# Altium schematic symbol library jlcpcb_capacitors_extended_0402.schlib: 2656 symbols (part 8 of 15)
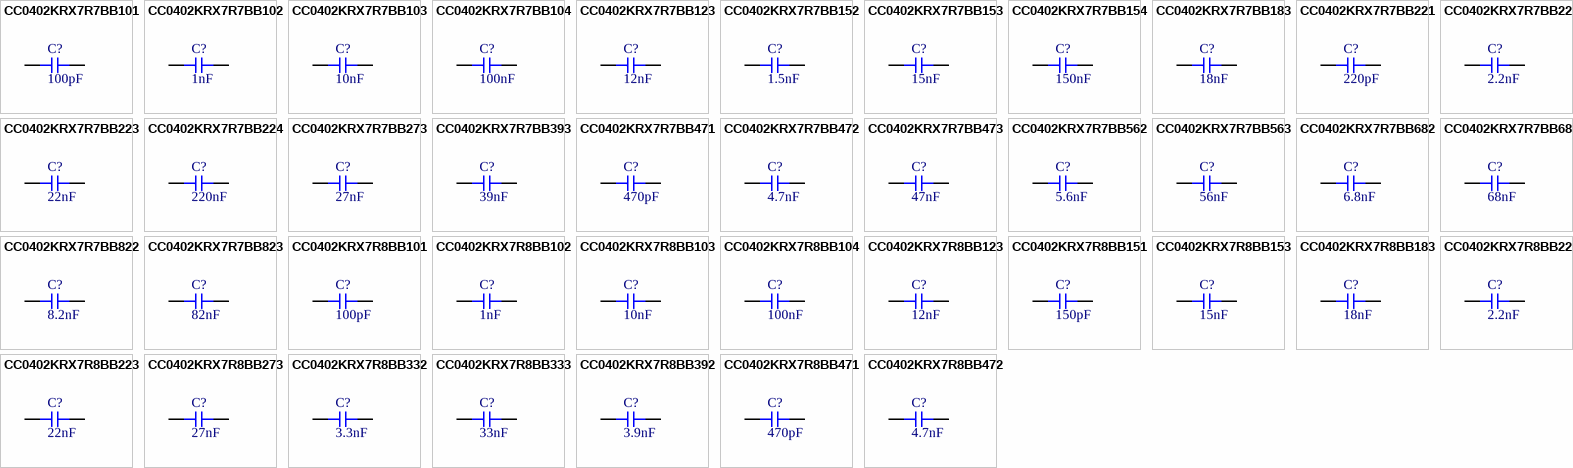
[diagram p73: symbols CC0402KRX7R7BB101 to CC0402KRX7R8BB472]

## CC0402KRX7R7BB104
designator C?  Capacitance: 100nF  (hidden comment: *)
Capacitor, Ceramic (MLCC), 100nF, ±10%, 16V, X7R, ±10%, SMD 0402; Manufacturer: YAGEO; Manufacturer Part Number: CC0402KRX7R7BB104
footprint CAP-0402 (0402 (1005M) Capacitor)
pins: 1, 2

## CC0402KRX7R7BB123
designator C?  Capacitance: 12nF  (hidden comment: *)
Capacitor, Ceramic (MLCC), 12nF, ±10%, 16V, X7R, ±10%, SMD 0402; Manufacturer: YAGEO; Manufacturer Part Number: CC0402KRX7R7BB123
footprint CAP-0402 (0402 (1005M) Capacitor)
pins: 1, 2

## CC0402KRX7R7BB152
designator C?  Capacitance: 1.5nF  (hidden comment: *)
Capacitor, Ceramic (MLCC), 1.5nF, ±10%, 16V, X7R, ±10%, SMD 0402; Manufacturer: YAGEO; Manufacturer Part Number: CC0402KRX7R7BB152
footprint CAP-0402 (0402 (1005M) Capacitor)
pins: 1, 2

## CC0402KRX7R7BB153
designator C?  Capacitance: 15nF  (hidden comment: *)
Capacitor, Ceramic (MLCC), 15nF, ±10%, 16V, X7R, ±10%, SMD 0402; Manufacturer: YAGEO; Manufacturer Part Number: CC0402KRX7R7BB153
footprint CAP-0402 (0402 (1005M) Capacitor)
pins: 1, 2

## CC0402KRX7R7BB154
designator C?  Capacitance: 150nF  (hidden comment: *)
Capacitor, Ceramic (MLCC), 150nF, ±10%, 16V, X7R, ±10%, SMD 0402; Manufacturer: YAGEO; Manufacturer Part Number: CC0402KRX7R7BB154
footprint CAP-0402 (0402 (1005M) Capacitor)
pins: 1, 2

## CC0402KRX7R7BB183
designator C?  Capacitance: 18nF  (hidden comment: *)
Capacitor, Ceramic (MLCC), 18nF, ±10%, 16V, X7R, ±10%, SMD 0402; Manufacturer: YAGEO; Manufacturer Part Number: CC0402KRX7R7BB183
footprint CAP-0402 (0402 (1005M) Capacitor)
pins: 1, 2

## CC0402KRX7R7BB221
designator C?  Capacitance: 220pF  (hidden comment: *)
Capacitor, Ceramic (MLCC), 220pF, ±10%, 16V, X7R, ±10%, SMD 0402; Manufacturer: YAGEO; Manufacturer Part Number: CC0402KRX7R7BB221
footprint CAP-0402 (0402 (1005M) Capacitor)
pins: 1, 2

## CC0402KRX7R7BB222
designator C?  Capacitance: 2.2nF  (hidden comment: *)
Capacitor, Ceramic (MLCC), 2.2nF, ±10%, 16V, X7R, ±10%, SMD 0402; Manufacturer: YAGEO; Manufacturer Part Number: CC0402KRX7R7BB222
footprint CAP-0402 (0402 (1005M) Capacitor)
pins: 1, 2

## CC0402KRX7R7BB223
designator C?  Capacitance: 22nF  (hidden comment: *)
Capacitor, Ceramic (MLCC), 22nF, ±10%, 16V, X7R, ±10%, SMD 0402; Manufacturer: YAGEO; Manufacturer Part Number: CC0402KRX7R7BB223
footprint CAP-0402 (0402 (1005M) Capacitor)
pins: 1, 2

## CC0402KRX7R7BB224
designator C?  Capacitance: 220nF  (hidden comment: *)
Capacitor, Ceramic (MLCC), 220nF, ±10%, 16V, X7R, ±10%, SMD 0402; Manufacturer: YAGEO; Manufacturer Part Number: CC0402KRX7R7BB224
footprint CAP-0402 (0402 (1005M) Capacitor)
pins: 1, 2

## CC0402KRX7R7BB273
designator C?  Capacitance: 27nF  (hidden comment: *)
Capacitor, Ceramic (MLCC), 27nF, ±10%, 16V, X7R, ±10%, SMD 0402; Manufacturer: YAGEO; Manufacturer Part Number: CC0402KRX7R7BB273
footprint CAP-0402 (0402 (1005M) Capacitor)
pins: 1, 2

## CC0402KRX7R7BB393
designator C?  Capacitance: 39nF  (hidden comment: *)
Capacitor, Ceramic (MLCC), 39nF, ±10%, 16V, X7R, ±10%, SMD 0402; Manufacturer: YAGEO; Manufacturer Part Number: CC0402KRX7R7BB393
footprint CAP-0402 (0402 (1005M) Capacitor)
pins: 1, 2

## CC0402KRX7R7BB471
designator C?  Capacitance: 470pF  (hidden comment: *)
Capacitor, Ceramic (MLCC), 470pF, ±10%, 16V, X7R, ±10%, SMD 0402; Manufacturer: YAGEO; Manufacturer Part Number: CC0402KRX7R7BB471
footprint CAP-0402 (0402 (1005M) Capacitor)
pins: 1, 2

## CC0402KRX7R7BB472
designator C?  Capacitance: 4.7nF  (hidden comment: *)
Capacitor, Ceramic (MLCC), 4.7nF, ±10%, 16V, X7R, ±10%, SMD 0402; Manufacturer: YAGEO; Manufacturer Part Number: CC0402KRX7R7BB472
footprint CAP-0402 (0402 (1005M) Capacitor)
pins: 1, 2

## CC0402KRX7R7BB473
designator C?  Capacitance: 47nF  (hidden comment: *)
Capacitor, Ceramic (MLCC), 47nF, ±10%, 16V, X7R, ±10%, SMD 0402; Manufacturer: YAGEO; Manufacturer Part Number: CC0402KRX7R7BB473
footprint CAP-0402 (0402 (1005M) Capacitor)
pins: 1, 2

## CC0402KRX7R7BB562
designator C?  Capacitance: 5.6nF  (hidden comment: *)
Capacitor, Ceramic (MLCC), 5.6nF, ±10%, 16V, X7R, ±10%, SMD 0402; Manufacturer: YAGEO; Manufacturer Part Number: CC0402KRX7R7BB562
footprint CAP-0402 (0402 (1005M) Capacitor)
pins: 1, 2

## CC0402KRX7R7BB563
designator C?  Capacitance: 56nF  (hidden comment: *)
Capacitor, Ceramic (MLCC), 56nF, ±10%, 16V, X7R, ±10%, SMD 0402; Manufacturer: YAGEO; Manufacturer Part Number: CC0402KRX7R7BB563
footprint CAP-0402 (0402 (1005M) Capacitor)
pins: 1, 2

## CC0402KRX7R7BB682
designator C?  Capacitance: 6.8nF  (hidden comment: *)
Capacitor, Ceramic (MLCC), 6.8nF, ±10%, 16V, X7R, ±10%, SMD 0402; Manufacturer: YAGEO; Manufacturer Part Number: CC0402KRX7R7BB682
footprint CAP-0402 (0402 (1005M) Capacitor)
pins: 1, 2

## CC0402KRX7R7BB683
designator C?  Capacitance: 68nF  (hidden comment: *)
Capacitor, Ceramic (MLCC), 68nF, ±10%, 16V, X7R, ±10%, SMD 0402; Manufacturer: YAGEO; Manufacturer Part Number: CC0402KRX7R7BB683
footprint CAP-0402 (0402 (1005M) Capacitor)
pins: 1, 2

## CC0402KRX7R7BB822
designator C?  Capacitance: 8.2nF  (hidden comment: *)
Capacitor, Ceramic (MLCC), 8.2nF, ±10%, 16V, X7R, ±10%, SMD 0402; Manufacturer: YAGEO; Manufacturer Part Number: CC0402KRX7R7BB822
footprint CAP-0402 (0402 (1005M) Capacitor)
pins: 1, 2

## CC0402KRX7R7BB823
designator C?  Capacitance: 82nF  (hidden comment: *)
Capacitor, Ceramic (MLCC), 82nF, ±10%, 16V, X7R, ±10%, SMD 0402; Manufacturer: YAGEO; Manufacturer Part Number: CC0402KRX7R7BB823
footprint CAP-0402 (0402 (1005M) Capacitor)
pins: 1, 2

## CC0402KRX7R8BB101
designator C?  Capacitance: 100pF  (hidden comment: *)
Capacitor, Ceramic (MLCC), 100pF, ±10%, 25V, X7R, ±10%, SMD 0402; Manufacturer: YAGEO; Manufacturer Part Number: CC0402KRX7R8BB101
footprint CAP-0402 (0402 (1005M) Capacitor)
pins: 1, 2

## CC0402KRX7R8BB102
designator C?  Capacitance: 1nF  (hidden comment: *)
Capacitor, Ceramic (MLCC), 1nF, ±10%, 25V, X7R, ±10%, SMD 0402; Manufacturer: YAGEO; Manufacturer Part Number: CC0402KRX7R8BB102
footprint CAP-0402 (0402 (1005M) Capacitor)
pins: 1, 2

## CC0402KRX7R8BB103
designator C?  Capacitance: 10nF  (hidden comment: *)
Capacitor, Ceramic (MLCC), 10nF, ±10%, 25V, X7R, ±10%, SMD 0402; Manufacturer: YAGEO; Manufacturer Part Number: CC0402KRX7R8BB103
footprint CAP-0402 (0402 (1005M) Capacitor)
pins: 1, 2

## CC0402KRX7R8BB104
designator C?  Capacitance: 100nF  (hidden comment: *)
Capacitor, Ceramic (MLCC), 100nF, ±10%, 25V, X7R, ±10%, SMD 0402; Manufacturer: YAGEO; Manufacturer Part Number: CC0402KRX7R8BB104
footprint CAP-0402 (0402 (1005M) Capacitor)
pins: 1, 2

## CC0402KRX7R8BB123
designator C?  Capacitance: 12nF  (hidden comment: *)
Capacitor, Ceramic (MLCC), 12nF, ±10%, 25V, X7R, ±10%, SMD 0402; Manufacturer: YAGEO; Manufacturer Part Number: CC0402KRX7R8BB123
footprint CAP-0402 (0402 (1005M) Capacitor)
pins: 1, 2

## CC0402KRX7R8BB151
designator C?  Capacitance: 150pF  (hidden comment: *)
Capacitor, Ceramic (MLCC), 150pF, ±10%, 25V, X7R, ±10%, SMD 0402; Manufacturer: YAGEO; Manufacturer Part Number: CC0402KRX7R8BB151
footprint CAP-0402 (0402 (1005M) Capacitor)
pins: 1, 2

## CC0402KRX7R8BB153
designator C?  Capacitance: 15nF  (hidden comment: *)
Capacitor, Ceramic (MLCC), 15nF, ±10%, 25V, X7R, ±10%, SMD 0402; Manufacturer: YAGEO; Manufacturer Part Number: CC0402KRX7R8BB153
footprint CAP-0402 (0402 (1005M) Capacitor)
pins: 1, 2

## CC0402KRX7R8BB183
designator C?  Capacitance: 18nF  (hidden comment: *)
Capacitor, Ceramic (MLCC), 18nF, ±10%, 25V, X7R, ±10%, SMD 0402; Manufacturer: YAGEO; Manufacturer Part Number: CC0402KRX7R8BB183
footprint CAP-0402 (0402 (1005M) Capacitor)
pins: 1, 2

## CC0402KRX7R8BB222
designator C?  Capacitance: 2.2nF  (hidden comment: *)
Capacitor, Ceramic (MLCC), 2.2nF, ±10%, 25V, X7R, ±10%, SMD 0402; Manufacturer: YAGEO; Manufacturer Part Number: CC0402KRX7R8BB222
footprint CAP-0402 (0402 (1005M) Capacitor)
pins: 1, 2

## CC0402KRX7R8BB223
designator C?  Capacitance: 22nF  (hidden comment: *)
Capacitor, Ceramic (MLCC), 22nF, ±10%, 25V, X7R, ±10%, SMD 0402; Manufacturer: YAGEO; Manufacturer Part Number: CC0402KRX7R8BB223
footprint CAP-0402 (0402 (1005M) Capacitor)
pins: 1, 2

## CC0402KRX7R8BB273
designator C?  Capacitance: 27nF  (hidden comment: *)
Capacitor, Ceramic (MLCC), 27nF, ±10%, 25V, X7R, ±10%, SMD 0402; Manufacturer: YAGEO; Manufacturer Part Number: CC0402KRX7R8BB273
footprint CAP-0402 (0402 (1005M) Capacitor)
pins: 1, 2

## CC0402KRX7R8BB332
designator C?  Capacitance: 3.3nF  (hidden comment: *)
Capacitor, Ceramic (MLCC), 3.3nF, ±10%, 25V, X7R, ±10%, SMD 0402; Manufacturer: YAGEO; Manufacturer Part Number: CC0402KRX7R8BB332
footprint CAP-0402 (0402 (1005M) Capacitor)
pins: 1, 2

## CC0402KRX7R8BB333
designator C?  Capacitance: 33nF  (hidden comment: *)
Capacitor, Ceramic (MLCC), 33nF, ±10%, 25V, X7R, ±10%, SMD 0402; Manufacturer: YAGEO; Manufacturer Part Number: CC0402KRX7R8BB333
footprint CAP-0402 (0402 (1005M) Capacitor)
pins: 1, 2

## CC0402KRX7R8BB392
designator C?  Capacitance: 3.9nF  (hidden comment: *)
Capacitor, Ceramic (MLCC), 3.9nF, ±10%, 25V, X7R, ±10%, SMD 0402; Manufacturer: YAGEO; Manufacturer Part Number: CC0402KRX7R8BB392
footprint CAP-0402 (0402 (1005M) Capacitor)
pins: 1, 2

## CC0402KRX7R8BB471
designator C?  Capacitance: 470pF  (hidden comment: *)
Capacitor, Ceramic (MLCC), 470pF, ±10%, 25V, X7R, ±10%, SMD 0402; Manufacturer: YAGEO; Manufacturer Part Number: CC0402KRX7R8BB471
footprint CAP-0402 (0402 (1005M) Capacitor)
pins: 1, 2

## CC0402KRX7R8BB472
designator C?  Capacitance: 4.7nF  (hidden comment: *)
Capacitor, Ceramic (MLCC), 4.7nF, ±10%, 25V, X7R, ±10%, SMD 0402; Manufacturer: YAGEO; Manufacturer Part Number: CC0402KRX7R8BB472
footprint CAP-0402 (0402 (1005M) Capacitor)
pins: 1, 2

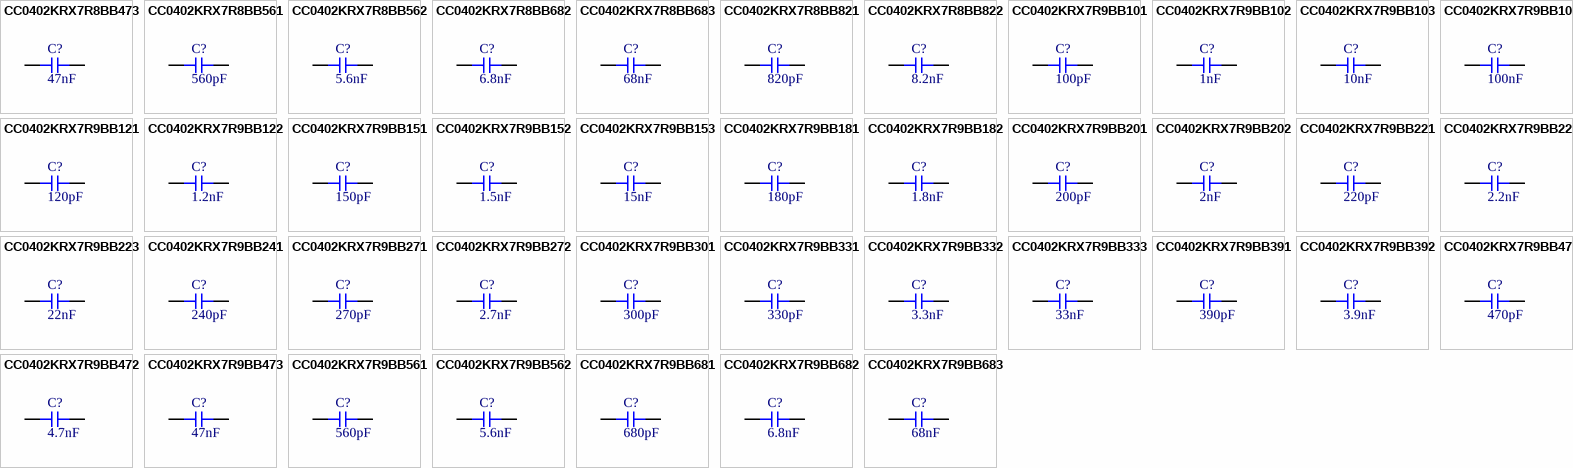
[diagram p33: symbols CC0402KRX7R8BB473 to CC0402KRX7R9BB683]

## CC0402KRX7R8BB473
designator C?  Capacitance: 47nF  (hidden comment: *)
Capacitor, Ceramic (MLCC), 47nF, ±10%, 25V, X7R, ±10%, SMD 0402; Manufacturer: YAGEO; Manufacturer Part Number: CC0402KRX7R8BB473
footprint CAP-0402 (0402 (1005M) Capacitor)
pins: 1, 2

## CC0402KRX7R8BB561
designator C?  Capacitance: 560pF  (hidden comment: *)
Capacitor, Ceramic (MLCC), 560pF, ±10%, 25V, X7R, ±10%, SMD 0402; Manufacturer: YAGEO; Manufacturer Part Number: CC0402KRX7R8BB561
footprint CAP-0402 (0402 (1005M) Capacitor)
pins: 1, 2

## CC0402KRX7R8BB562
designator C?  Capacitance: 5.6nF  (hidden comment: *)
Capacitor, Ceramic (MLCC), 5.6nF, ±10%, 25V, X7R, ±10%, SMD 0402; Manufacturer: YAGEO; Manufacturer Part Number: CC0402KRX7R8BB562
footprint CAP-0402 (0402 (1005M) Capacitor)
pins: 1, 2

## CC0402KRX7R8BB682
designator C?  Capacitance: 6.8nF  (hidden comment: *)
Capacitor, Ceramic (MLCC), 6.8nF, ±10%, 25V, X7R, ±10%, SMD 0402; Manufacturer: YAGEO; Manufacturer Part Number: CC0402KRX7R8BB682
footprint CAP-0402 (0402 (1005M) Capacitor)
pins: 1, 2

## CC0402KRX7R8BB683
designator C?  Capacitance: 68nF  (hidden comment: *)
Capacitor, Ceramic (MLCC), 68nF, ±10%, 25V, X7R, ±10%, SMD 0402; Manufacturer: YAGEO; Manufacturer Part Number: CC0402KRX7R8BB683
footprint CAP-0402 (0402 (1005M) Capacitor)
pins: 1, 2

## CC0402KRX7R8BB821
designator C?  Capacitance: 820pF  (hidden comment: *)
Capacitor, Ceramic (MLCC), 820pF, ±10%, 25V, X7R, ±10%, SMD 0402; Manufacturer: YAGEO; Manufacturer Part Number: CC0402KRX7R8BB821
footprint CAP-0402 (0402 (1005M) Capacitor)
pins: 1, 2

## CC0402KRX7R8BB822
designator C?  Capacitance: 8.2nF  (hidden comment: *)
Capacitor, Ceramic (MLCC), 8.2nF, ±10%, 25V, X7R, ±10%, SMD 0402; Manufacturer: YAGEO; Manufacturer Part Number: CC0402KRX7R8BB822
footprint CAP-0402 (0402 (1005M) Capacitor)
pins: 1, 2

## CC0402KRX7R9BB101
designator C?  Capacitance: 100pF  (hidden comment: *)
Capacitor, Ceramic (MLCC), 100pF, ±10%, 50V, X7R, ±10%, SMD 0402; Manufacturer: YAGEO; Manufacturer Part Number: CC0402KRX7R9BB101
footprint CAP-0402 (0402 (1005M) Capacitor)
pins: 1, 2

## CC0402KRX7R9BB102
designator C?  Capacitance: 1nF  (hidden comment: *)
Capacitor, Ceramic (MLCC), 1nF, ±10%, 50V, X7R, ±10%, SMD 0402; Manufacturer: YAGEO; Manufacturer Part Number: CC0402KRX7R9BB102
footprint CAP-0402 (0402 (1005M) Capacitor)
pins: 1, 2

## CC0402KRX7R9BB103
designator C?  Capacitance: 10nF  (hidden comment: *)
Capacitor, Ceramic (MLCC), 10nF, ±10%, 50V, X7R, ±10%, SMD 0402; Manufacturer: YAGEO; Manufacturer Part Number: CC0402KRX7R9BB103
footprint CAP-0402 (0402 (1005M) Capacitor)
pins: 1, 2

## CC0402KRX7R9BB104
designator C?  Capacitance: 100nF  (hidden comment: *)
Capacitor, Ceramic (MLCC), 100nF, ±10%, 50V, X7R, ±10%, SMD 0402; Manufacturer: YAGEO; Manufacturer Part Number: CC0402KRX7R9BB104
footprint CAP-0402 (0402 (1005M) Capacitor)
pins: 1, 2

## CC0402KRX7R9BB121
designator C?  Capacitance: 120pF  (hidden comment: *)
Capacitor, Ceramic (MLCC), 120pF, ±10%, 50V, X7R, ±10%, SMD 0402; Manufacturer: YAGEO; Manufacturer Part Number: CC0402KRX7R9BB121
footprint CAP-0402 (0402 (1005M) Capacitor)
pins: 1, 2

## CC0402KRX7R9BB122
designator C?  Capacitance: 1.2nF  (hidden comment: *)
Capacitor, Ceramic (MLCC), 1.2nF, ±10%, 50V, X7R, ±10%, SMD 0402; Manufacturer: YAGEO; Manufacturer Part Number: CC0402KRX7R9BB122
footprint CAP-0402 (0402 (1005M) Capacitor)
pins: 1, 2

## CC0402KRX7R9BB151
designator C?  Capacitance: 150pF  (hidden comment: *)
Capacitor, Ceramic (MLCC), 150pF, ±10%, 50V, X7R, ±10%, SMD 0402; Manufacturer: YAGEO; Manufacturer Part Number: CC0402KRX7R9BB151
footprint CAP-0402 (0402 (1005M) Capacitor)
pins: 1, 2

## CC0402KRX7R9BB152
designator C?  Capacitance: 1.5nF  (hidden comment: *)
Capacitor, Ceramic (MLCC), 1.5nF, ±10%, 50V, X7R, ±10%, SMD 0402; Manufacturer: YAGEO; Manufacturer Part Number: CC0402KRX7R9BB152
footprint CAP-0402 (0402 (1005M) Capacitor)
pins: 1, 2

## CC0402KRX7R9BB153
designator C?  Capacitance: 15nF  (hidden comment: *)
Capacitor, Ceramic (MLCC), 15nF, ±10%, 50V, X7R, ±10%, SMD 0402; Manufacturer: YAGEO; Manufacturer Part Number: CC0402KRX7R9BB153
footprint CAP-0402 (0402 (1005M) Capacitor)
pins: 1, 2

## CC0402KRX7R9BB181
designator C?  Capacitance: 180pF  (hidden comment: *)
Capacitor, Ceramic (MLCC), 180pF, ±10%, 50V, X7R, ±10%, SMD 0402; Manufacturer: YAGEO; Manufacturer Part Number: CC0402KRX7R9BB181
footprint CAP-0402 (0402 (1005M) Capacitor)
pins: 1, 2

## CC0402KRX7R9BB182
designator C?  Capacitance: 1.8nF  (hidden comment: *)
Capacitor, Ceramic (MLCC), 1.8nF, ±10%, 50V, X7R, ±10%, SMD 0402; Manufacturer: YAGEO; Manufacturer Part Number: CC0402KRX7R9BB182
footprint CAP-0402 (0402 (1005M) Capacitor)
pins: 1, 2

## CC0402KRX7R9BB201
designator C?  Capacitance: 200pF  (hidden comment: *)
Capacitor, Ceramic (MLCC), 200pF, ±10%, 50V, X7R, ±10%, SMD 0402; Manufacturer: YAGEO; Manufacturer Part Number: CC0402KRX7R9BB201
footprint CAP-0402 (0402 (1005M) Capacitor)
pins: 1, 2

## CC0402KRX7R9BB202
designator C?  Capacitance: 2nF  (hidden comment: *)
Capacitor, Ceramic (MLCC), 2nF, ±10%, 50V, X7R, ±10%, SMD 0402; Manufacturer: YAGEO; Manufacturer Part Number: CC0402KRX7R9BB202
footprint CAP-0402 (0402 (1005M) Capacitor)
pins: 1, 2

## CC0402KRX7R9BB221
designator C?  Capacitance: 220pF  (hidden comment: *)
Capacitor, Ceramic (MLCC), 220pF, ±10%, 50V, X7R, ±10%, SMD 0402; Manufacturer: YAGEO; Manufacturer Part Number: CC0402KRX7R9BB221
footprint CAP-0402 (0402 (1005M) Capacitor)
pins: 1, 2

## CC0402KRX7R9BB222
designator C?  Capacitance: 2.2nF  (hidden comment: *)
Capacitor, Ceramic (MLCC), 2.2nF, ±10%, 50V, X7R, ±10%, SMD 0402; Manufacturer: YAGEO; Manufacturer Part Number: CC0402KRX7R9BB222
footprint CAP-0402 (0402 (1005M) Capacitor)
pins: 1, 2

## CC0402KRX7R9BB223
designator C?  Capacitance: 22nF  (hidden comment: *)
Capacitor, Ceramic (MLCC), 22nF, ±10%, 50V, X7R, ±10%, SMD 0402; Manufacturer: YAGEO; Manufacturer Part Number: CC0402KRX7R9BB223
footprint CAP-0402 (0402 (1005M) Capacitor)
pins: 1, 2

## CC0402KRX7R9BB241
designator C?  Capacitance: 240pF  (hidden comment: *)
Capacitor, Ceramic (MLCC), 240pF, ±10%, 50V, X7R, ±10%, SMD 0402; Manufacturer: YAGEO; Manufacturer Part Number: CC0402KRX7R9BB241
footprint CAP-0402 (0402 (1005M) Capacitor)
pins: 1, 2

## CC0402KRX7R9BB271
designator C?  Capacitance: 270pF  (hidden comment: *)
Capacitor, Ceramic (MLCC), 270pF, ±10%, 50V, X7R, ±10%, SMD 0402; Manufacturer: YAGEO; Manufacturer Part Number: CC0402KRX7R9BB271
footprint CAP-0402 (0402 (1005M) Capacitor)
pins: 1, 2

## CC0402KRX7R9BB272
designator C?  Capacitance: 2.7nF  (hidden comment: *)
Capacitor, Ceramic (MLCC), 2.7nF, ±10%, 50V, X7R, ±10%, SMD 0402; Manufacturer: YAGEO; Manufacturer Part Number: CC0402KRX7R9BB272
footprint CAP-0402 (0402 (1005M) Capacitor)
pins: 1, 2

## CC0402KRX7R9BB301
designator C?  Capacitance: 300pF  (hidden comment: *)
Capacitor, Ceramic (MLCC), 300pF, ±10%, 50V, X7R, ±10%, SMD 0402; Manufacturer: YAGEO; Manufacturer Part Number: CC0402KRX7R9BB301
footprint CAP-0402 (0402 (1005M) Capacitor)
pins: 1, 2

## CC0402KRX7R9BB331
designator C?  Capacitance: 330pF  (hidden comment: *)
Capacitor, Ceramic (MLCC), 330pF, ±10%, 50V, X7R, ±10%, SMD 0402; Manufacturer: YAGEO; Manufacturer Part Number: CC0402KRX7R9BB331
footprint CAP-0402 (0402 (1005M) Capacitor)
pins: 1, 2

## CC0402KRX7R9BB332
designator C?  Capacitance: 3.3nF  (hidden comment: *)
Capacitor, Ceramic (MLCC), 3.3nF, ±10%, 50V, X7R, ±10%, SMD 0402; Manufacturer: YAGEO; Manufacturer Part Number: CC0402KRX7R9BB332
footprint CAP-0402 (0402 (1005M) Capacitor)
pins: 1, 2

## CC0402KRX7R9BB333
designator C?  Capacitance: 33nF  (hidden comment: *)
Capacitor, Ceramic (MLCC), 33nF, ±10%, 50V, X7R, ±10%, SMD 0402; Manufacturer: YAGEO; Manufacturer Part Number: CC0402KRX7R9BB333
footprint CAP-0402 (0402 (1005M) Capacitor)
pins: 1, 2

## CC0402KRX7R9BB391
designator C?  Capacitance: 390pF  (hidden comment: *)
Capacitor, Ceramic (MLCC), 390pF, ±10%, 50V, X7R, ±10%, SMD 0402; Manufacturer: YAGEO; Manufacturer Part Number: CC0402KRX7R9BB391
footprint CAP-0402 (0402 (1005M) Capacitor)
pins: 1, 2

## CC0402KRX7R9BB392
designator C?  Capacitance: 3.9nF  (hidden comment: *)
Capacitor, Ceramic (MLCC), 3.9nF, ±10%, 50V, X7R, ±10%, SMD 0402; Manufacturer: YAGEO; Manufacturer Part Number: CC0402KRX7R9BB392
footprint CAP-0402 (0402 (1005M) Capacitor)
pins: 1, 2

## CC0402KRX7R9BB471
designator C?  Capacitance: 470pF  (hidden comment: *)
Capacitor, Ceramic (MLCC), 470pF, ±10%, 50V, X7R, ±10%, SMD 0402; Manufacturer: YAGEO; Manufacturer Part Number: CC0402KRX7R9BB471
footprint CAP-0402 (0402 (1005M) Capacitor)
pins: 1, 2

## CC0402KRX7R9BB472
designator C?  Capacitance: 4.7nF  (hidden comment: *)
Capacitor, Ceramic (MLCC), 4.7nF, ±10%, 50V, X7R, ±10%, SMD 0402; Manufacturer: YAGEO; Manufacturer Part Number: CC0402KRX7R9BB472
footprint CAP-0402 (0402 (1005M) Capacitor)
pins: 1, 2

## CC0402KRX7R9BB473
designator C?  Capacitance: 47nF  (hidden comment: *)
Capacitor, Ceramic (MLCC), 47nF, ±10%, 50V, X7R, ±10%, SMD 0402; Manufacturer: YAGEO; Manufacturer Part Number: CC0402KRX7R9BB473
footprint CAP-0402 (0402 (1005M) Capacitor)
pins: 1, 2

## CC0402KRX7R9BB561
designator C?  Capacitance: 560pF  (hidden comment: *)
Capacitor, Ceramic (MLCC), 560pF, ±10%, 50V, X7R, ±10%, SMD 0402; Manufacturer: YAGEO; Manufacturer Part Number: CC0402KRX7R9BB561
footprint CAP-0402 (0402 (1005M) Capacitor)
pins: 1, 2

## CC0402KRX7R9BB562
designator C?  Capacitance: 5.6nF  (hidden comment: *)
Capacitor, Ceramic (MLCC), 5.6nF, ±10%, 50V, X7R, ±10%, SMD 0402; Manufacturer: YAGEO; Manufacturer Part Number: CC0402KRX7R9BB562
footprint CAP-0402 (0402 (1005M) Capacitor)
pins: 1, 2

## CC0402KRX7R9BB681
designator C?  Capacitance: 680pF  (hidden comment: *)
Capacitor, Ceramic (MLCC), 680pF, ±10%, 50V, X7R, ±10%, SMD 0402; Manufacturer: YAGEO; Manufacturer Part Number: CC0402KRX7R9BB681
footprint CAP-0402 (0402 (1005M) Capacitor)
pins: 1, 2

## CC0402KRX7R9BB682
designator C?  Capacitance: 6.8nF  (hidden comment: *)
Capacitor, Ceramic (MLCC), 6.8nF, ±10%, 50V, X7R, ±10%, SMD 0402; Manufacturer: YAGEO; Manufacturer Part Number: CC0402KRX7R9BB682
footprint CAP-0402 (0402 (1005M) Capacitor)
pins: 1, 2

## CC0402KRX7R9BB683
designator C?  Capacitance: 68nF  (hidden comment: *)
Capacitor, Ceramic (MLCC), 68nF, ±10%, 50V, X7R, ±10%, SMD 0402; Manufacturer: YAGEO; Manufacturer Part Number: CC0402KRX7R9BB683
footprint CAP-0402 (0402 (1005M) Capacitor)
pins: 1, 2

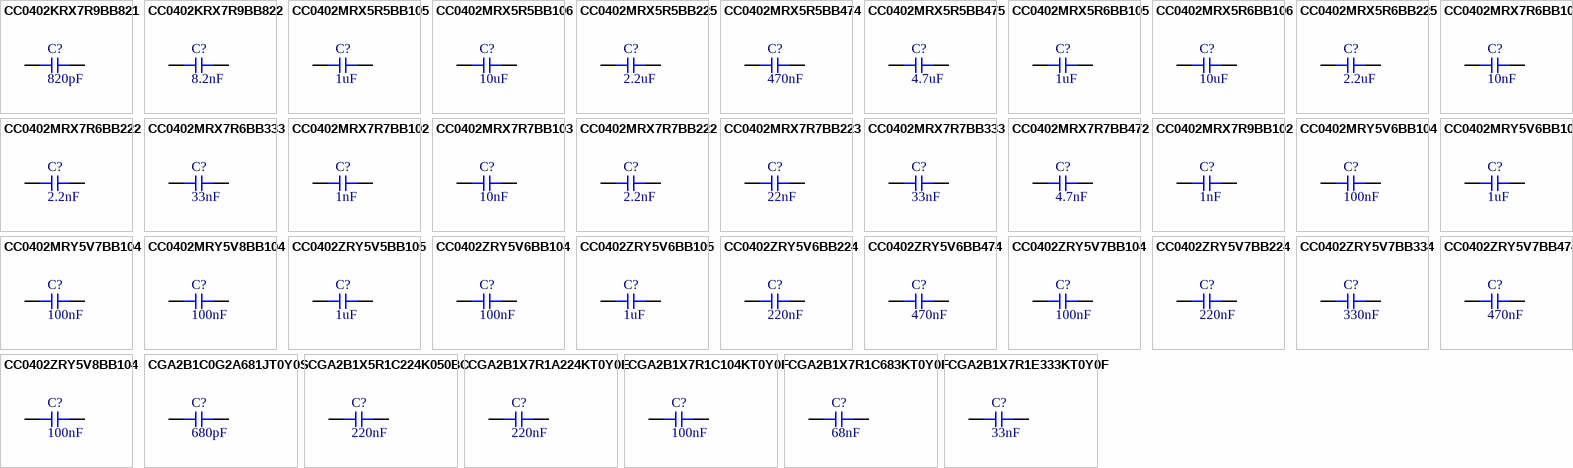
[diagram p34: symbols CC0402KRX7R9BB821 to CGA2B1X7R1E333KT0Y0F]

## CC0402KRX7R9BB821
designator C?  Capacitance: 820pF  (hidden comment: *)
Capacitor, Ceramic (MLCC), 820pF, ±10%, 50V, X7R, ±10%, SMD 0402; Manufacturer: YAGEO; Manufacturer Part Number: CC0402KRX7R9BB821
footprint CAP-0402 (0402 (1005M) Capacitor)
pins: 1, 2

## CC0402KRX7R9BB822
designator C?  Capacitance: 8.2nF  (hidden comment: *)
Capacitor, Ceramic (MLCC), 8.2nF, ±10%, 50V, X7R, ±10%, SMD 0402; Manufacturer: YAGEO; Manufacturer Part Number: CC0402KRX7R9BB822
footprint CAP-0402 (0402 (1005M) Capacitor)
pins: 1, 2

## CC0402MRX5R5BB105
designator C?  Capacitance: 1uF  (hidden comment: *)
Capacitor, Ceramic (MLCC), 1uF, ±20%, 6.3V, X5R, ±20%, SMD 0402; Manufacturer: YAGEO; Manufacturer Part Number: CC0402MRX5R5BB105
footprint CAP-0402 (0402 (1005M) Capacitor)
pins: 1, 2

## CC0402MRX5R5BB106
designator C?  Capacitance: 10uF  (hidden comment: *)
Capacitor, Ceramic (MLCC), 10uF, ±20%, 6.3V, X5R, ±20%, SMD 0402; Manufacturer: YAGEO; Manufacturer Part Number: CC0402MRX5R5BB106
footprint CAP-0402 (0402 (1005M) Capacitor)
pins: 1, 2

## CC0402MRX5R5BB225
designator C?  Capacitance: 2.2uF  (hidden comment: *)
Capacitor, Ceramic (MLCC), 2.2uF, ±20%, 6.3V, X5R, ±20%, SMD 0402; Manufacturer: YAGEO; Manufacturer Part Number: CC0402MRX5R5BB225
footprint CAP-0402 (0402 (1005M) Capacitor)
pins: 1, 2

## CC0402MRX5R5BB474
designator C?  Capacitance: 470nF  (hidden comment: *)
Capacitor, Ceramic (MLCC), 470nF, ±20%, 6.3V, X5R, ±20%, SMD 0402; Manufacturer: YAGEO; Manufacturer Part Number: CC0402MRX5R5BB474
footprint CAP-0402 (0402 (1005M) Capacitor)
pins: 1, 2

## CC0402MRX5R5BB475
designator C?  Capacitance: 4.7uF  (hidden comment: *)
Capacitor, Ceramic (MLCC), 4.7uF, ±20%, 6.3V, X5R, ±20%, SMD 0402; Manufacturer: YAGEO; Manufacturer Part Number: CC0402MRX5R5BB475
footprint CAP-0402 (0402 (1005M) Capacitor)
pins: 1, 2

## CC0402MRX5R6BB105
designator C?  Capacitance: 1uF  (hidden comment: *)
Capacitor, Ceramic (MLCC), 1uF, ±20%, 10V, X5R, ±20%, SMD 0402; Manufacturer: YAGEO; Manufacturer Part Number: CC0402MRX5R6BB105
footprint CAP-0402 (0402 (1005M) Capacitor)
pins: 1, 2

## CC0402MRX5R6BB106
designator C?  Capacitance: 10uF  (hidden comment: *)
Capacitor, Ceramic (MLCC), 10uF, ±20%, 10V, X5R, ±20%, SMD 0402; Manufacturer: YAGEO; Manufacturer Part Number: CC0402MRX5R6BB106
footprint CAP-0402 (0402 (1005M) Capacitor)
pins: 1, 2

## CC0402MRX5R6BB225
designator C?  Capacitance: 2.2uF  (hidden comment: *)
Capacitor, Ceramic (MLCC), 2.2uF, ±20%, 10V, X5R, ±20%, SMD 0402; Manufacturer: YAGEO; Manufacturer Part Number: CC0402MRX5R6BB225
footprint CAP-0402 (0402 (1005M) Capacitor)
pins: 1, 2

## CC0402MRX7R6BB103
designator C?  Capacitance: 10nF  (hidden comment: *)
Capacitor, Ceramic (MLCC), 10nF, ±20%, 10V, X7R, ±20%, SMD 0402; Manufacturer: YAGEO; Manufacturer Part Number: CC0402MRX7R6BB103
footprint CAP-0402 (0402 (1005M) Capacitor)
pins: 1, 2

## CC0402MRX7R6BB222
designator C?  Capacitance: 2.2nF  (hidden comment: *)
Capacitor, Ceramic (MLCC), 2.2nF, ±20%, 10V, X7R, ±20%, SMD 0402; Manufacturer: YAGEO; Manufacturer Part Number: CC0402MRX7R6BB222
footprint CAP-0402 (0402 (1005M) Capacitor)
pins: 1, 2

## CC0402MRX7R6BB333
designator C?  Capacitance: 33nF  (hidden comment: *)
Capacitor, Ceramic (MLCC), 33nF, ±20%, 10V, X7R, ±20%, SMD 0402; Manufacturer: YAGEO; Manufacturer Part Number: CC0402MRX7R6BB333
footprint CAP-0402 (0402 (1005M) Capacitor)
pins: 1, 2

## CC0402MRX7R7BB102
designator C?  Capacitance: 1nF  (hidden comment: *)
Capacitor, Ceramic (MLCC), 1nF, ±20%, 16V, X7R, ±20%, SMD 0402; Manufacturer: YAGEO; Manufacturer Part Number: CC0402MRX7R7BB102
footprint CAP-0402 (0402 (1005M) Capacitor)
pins: 1, 2

## CC0402MRX7R7BB103
designator C?  Capacitance: 10nF  (hidden comment: *)
Capacitor, Ceramic (MLCC), 10nF, ±20%, 16V, X7R, ±20%, SMD 0402; Manufacturer: YAGEO; Manufacturer Part Number: CC0402MRX7R7BB103
footprint CAP-0402 (0402 (1005M) Capacitor)
pins: 1, 2

## CC0402MRX7R7BB222
designator C?  Capacitance: 2.2nF  (hidden comment: *)
Capacitor, Ceramic (MLCC), 2.2nF, ±20%, 16V, X7R, ±20%, SMD 0402; Manufacturer: YAGEO; Manufacturer Part Number: CC0402MRX7R7BB222
footprint CAP-0402 (0402 (1005M) Capacitor)
pins: 1, 2

## CC0402MRX7R7BB223
designator C?  Capacitance: 22nF  (hidden comment: *)
Capacitor, Ceramic (MLCC), 22nF, ±20%, 16V, X7R, ±20%, SMD 0402; Manufacturer: YAGEO; Manufacturer Part Number: CC0402MRX7R7BB223
footprint CAP-0402 (0402 (1005M) Capacitor)
pins: 1, 2

## CC0402MRX7R7BB333
designator C?  Capacitance: 33nF  (hidden comment: *)
Capacitor, Ceramic (MLCC), 33nF, ±20%, 16V, X7R, ±20%, SMD 0402; Manufacturer: YAGEO; Manufacturer Part Number: CC0402MRX7R7BB333
footprint CAP-0402 (0402 (1005M) Capacitor)
pins: 1, 2

## CC0402MRX7R7BB472
designator C?  Capacitance: 4.7nF  (hidden comment: *)
Capacitor, Ceramic (MLCC), 4.7nF, ±20%, 16V, X7R, ±20%, SMD 0402; Manufacturer: YAGEO; Manufacturer Part Number: CC0402MRX7R7BB472
footprint CAP-0402 (0402 (1005M) Capacitor)
pins: 1, 2

## CC0402MRX7R9BB102
designator C?  Capacitance: 1nF  (hidden comment: *)
Capacitor, Ceramic (MLCC), 1nF, ±20%, 50V, X7R, ±20%, SMD 0402; Manufacturer: YAGEO; Manufacturer Part Number: CC0402MRX7R9BB102
footprint CAP-0402 (0402 (1005M) Capacitor)
pins: 1, 2

## CC0402MRY5V6BB104
designator C?  Capacitance: 100nF  (hidden comment: *)
Capacitor, Ceramic (MLCC), 100nF, ±20%, 10V, Y5V, ±20%, SMD 0402; Manufacturer: YAGEO; Manufacturer Part Number: CC0402MRY5V6BB104
footprint CAP-0402 (0402 (1005M) Capacitor)
pins: 1, 2

## CC0402MRY5V6BB105
designator C?  Capacitance: 1uF  (hidden comment: *)
Capacitor, Ceramic (MLCC), 1uF, ±20%, 10V, Y5V, ±20%, SMD 0402; Manufacturer: YAGEO; Manufacturer Part Number: CC0402MRY5V6BB105
footprint CAP-0402 (0402 (1005M) Capacitor)
pins: 1, 2

## CC0402MRY5V7BB104
designator C?  Capacitance: 100nF  (hidden comment: *)
Capacitor, Ceramic (MLCC), 100nF, ±20%, 16V, Y5V, ±20%, SMD 0402; Manufacturer: YAGEO; Manufacturer Part Number: CC0402MRY5V7BB104
footprint CAP-0402 (0402 (1005M) Capacitor)
pins: 1, 2

## CC0402MRY5V8BB104
designator C?  Capacitance: 100nF  (hidden comment: *)
Capacitor, Ceramic (MLCC), 100nF, ±20%, 25V, Y5V, ±20%, SMD 0402; Manufacturer: YAGEO; Manufacturer Part Number: CC0402MRY5V8BB104
footprint CAP-0402 (0402 (1005M) Capacitor)
pins: 1, 2

## CC0402ZRY5V5BB105
designator C?  Capacitance: 1uF  (hidden comment: *)
Capacitor, Ceramic (MLCC), 1uF, 6.3V, Y5V, SMD 0402; Manufacturer: YAGEO; Manufacturer Part Number: CC0402ZRY5V5BB105; Temperature Rating: -20%~+80%
footprint CAP-0402 (0402 (1005M) Capacitor)
pins: 1, 2

## CC0402ZRY5V6BB104
designator C?  Capacitance: 100nF  (hidden comment: *)
Capacitor, Ceramic (MLCC), 100nF, 10V, Y5V, SMD 0402; Manufacturer: YAGEO; Manufacturer Part Number: CC0402ZRY5V6BB104; Temperature Rating: -20%~+80%
footprint CAP-0402 (0402 (1005M) Capacitor)
pins: 1, 2

## CC0402ZRY5V6BB105
designator C?  Capacitance: 1uF  (hidden comment: *)
Capacitor, Ceramic (MLCC), 1uF, 10V, Y5V, SMD 0402; Manufacturer: YAGEO; Manufacturer Part Number: CC0402ZRY5V6BB105; Temperature Rating: -20%~+80%
footprint CAP-0402 (0402 (1005M) Capacitor)
pins: 1, 2

## CC0402ZRY5V6BB224
designator C?  Capacitance: 220nF  (hidden comment: *)
Capacitor, Ceramic (MLCC), 220nF, 10V, Y5V, SMD 0402; Manufacturer: YAGEO; Manufacturer Part Number: CC0402ZRY5V6BB224; Temperature Rating: -20%~+80%
footprint CAP-0402 (0402 (1005M) Capacitor)
pins: 1, 2

## CC0402ZRY5V6BB474
designator C?  Capacitance: 470nF  (hidden comment: *)
Capacitor, Ceramic (MLCC), 470nF, 10V, Y5V, SMD 0402; Manufacturer: YAGEO; Manufacturer Part Number: CC0402ZRY5V6BB474; Temperature Rating: -20%~+80%
footprint CAP-0402 (0402 (1005M) Capacitor)
pins: 1, 2

## CC0402ZRY5V7BB104
designator C?  Capacitance: 100nF  (hidden comment: *)
Capacitor, Ceramic (MLCC), 100nF, 16V, Y5V, SMD 0402; Manufacturer: YAGEO; Manufacturer Part Number: CC0402ZRY5V7BB104; Temperature Rating: -20%~+80%
footprint CAP-0402 (0402 (1005M) Capacitor)
pins: 1, 2

## CC0402ZRY5V7BB224
designator C?  Capacitance: 220nF  (hidden comment: *)
Capacitor, Ceramic (MLCC), 220nF, 16V, Y5V, SMD 0402; Manufacturer: YAGEO; Manufacturer Part Number: CC0402ZRY5V7BB224; Temperature Rating: -20%~+80%
footprint CAP-0402 (0402 (1005M) Capacitor)
pins: 1, 2

## CC0402ZRY5V7BB334
designator C?  Capacitance: 330nF  (hidden comment: *)
Capacitor, Ceramic (MLCC), 330nF, 16V, Y5V, SMD 0402; Manufacturer: YAGEO; Manufacturer Part Number: CC0402ZRY5V7BB334; Temperature Rating: -20%~+80%
footprint CAP-0402 (0402 (1005M) Capacitor)
pins: 1, 2

## CC0402ZRY5V7BB474
designator C?  Capacitance: 470nF  (hidden comment: *)
Capacitor, Ceramic (MLCC), 470nF, 16V, Y5V, SMD 0402; Manufacturer: YAGEO; Manufacturer Part Number: CC0402ZRY5V7BB474; Temperature Rating: -20%~+80%
footprint CAP-0402 (0402 (1005M) Capacitor)
pins: 1, 2

## CC0402ZRY5V8BB104
designator C?  Capacitance: 100nF  (hidden comment: *)
Capacitor, Ceramic (MLCC), 100nF, 25V, Y5V, SMD 0402; Manufacturer: YAGEO; Manufacturer Part Number: CC0402ZRY5V8BB104; Temperature Rating: -20%~+80%
footprint CAP-0402 (0402 (1005M) Capacitor)
pins: 1, 2

## CGA2B1C0G2A681JT0Y0S
designator C?  Capacitance: 680pF  (hidden comment: *)
Capacitor, Ceramic (MLCC), 680pF, ±5%, 100V, C0G, ±5%, SMD 0402; Manufacturer: TDK; Manufacturer Part Number: CGA2B1C0G2A681JT0Y0S
footprint CAP-0402 (0402 (1005M) Capacitor)
pins: 1, 2

## CGA2B1X5R1C224K050BC
designator C?  Capacitance: 220nF  (hidden comment: *)
Capacitor, Ceramic (MLCC), 220nF, ±10%, 16V, X5R, ±10%, SMD 0402; Manufacturer: TDK; Manufacturer Part Number: CGA2B1X5R1C224K050BC
footprint CAP-0402 (0402 (1005M) Capacitor)
pins: 1, 2

## CGA2B1X7R1A224KT0Y0E
designator C?  Capacitance: 220nF  (hidden comment: *)
Capacitor, Ceramic (MLCC), 220nF, ±10%, 10V, X7R, ±10%, SMD 0402; Manufacturer: TDK; Manufacturer Part Number: CGA2B1X7R1A224KT0Y0E
footprint CAP-0402 (0402 (1005M) Capacitor)
pins: 1, 2

## CGA2B1X7R1C104KT0Y0F
designator C?  Capacitance: 100nF  (hidden comment: *)
Capacitor, Ceramic (MLCC), 100nF, ±10%, 16V, X7R, ±10%, SMD 0402; Manufacturer: TDK; Manufacturer Part Number: CGA2B1X7R1C104KT0Y0F
footprint CAP-0402 (0402 (1005M) Capacitor)
pins: 1, 2

## CGA2B1X7R1C683KT0Y0F
designator C?  Capacitance: 68nF  (hidden comment: *)
Capacitor, Ceramic (MLCC), 68nF, ±10%, 16V, X7R, ±10%, SMD 0402; Manufacturer: TDK; Manufacturer Part Number: CGA2B1X7R1C683KT0Y0F
footprint CAP-0402 (0402 (1005M) Capacitor)
pins: 1, 2

## CGA2B1X7R1E333KT0Y0F
designator C?  Capacitance: 33nF  (hidden comment: *)
Capacitor, Ceramic (MLCC), 33nF, ±10%, 25V, X7R, ±10%, SMD 0402; Manufacturer: TDK; Manufacturer Part Number: CGA2B1X7R1E333KT0Y0F
footprint CAP-0402 (0402 (1005M) Capacitor)
pins: 1, 2

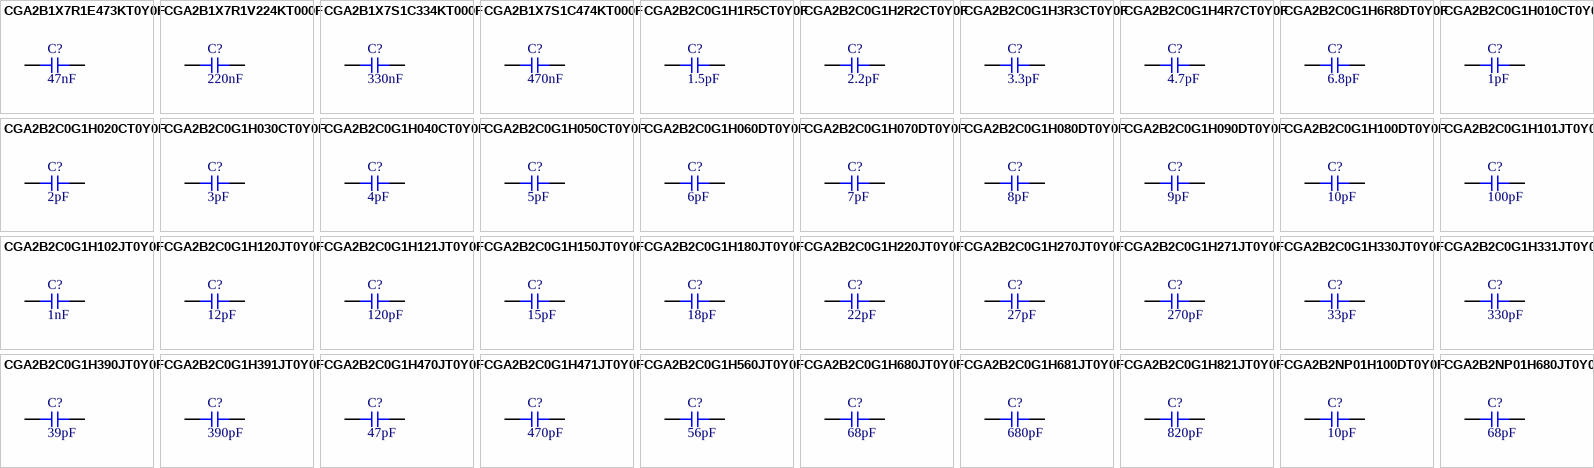
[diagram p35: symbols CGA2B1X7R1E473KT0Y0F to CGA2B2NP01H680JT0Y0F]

## CGA2B1X7R1E473KT0Y0F
designator C?  Capacitance: 47nF  (hidden comment: *)
Capacitor, Ceramic (MLCC), 47nF, ±10%, 25V, X7R, ±10%, SMD 0402; Manufacturer: TDK; Manufacturer Part Number: CGA2B1X7R1E473KT0Y0F
footprint CAP-0402 (0402 (1005M) Capacitor)
pins: 1, 2

## CGA2B1X7R1V224KT000F
designator C?  Capacitance: 220nF  (hidden comment: *)
Capacitor, Ceramic (MLCC), 220nF, ±10%, 35V, X7R, ±10%, SMD 0402; Manufacturer: TDK; Manufacturer Part Number: CGA2B1X7R1V224KT000F
footprint CAP-0402 (0402 (1005M) Capacitor)
pins: 1, 2

## CGA2B1X7S1C334KT000F
designator C?  Capacitance: 330nF  (hidden comment: *)
Capacitor, Ceramic (MLCC), 330nF, ±10%, 16V, X7S, ±10%, SMD 0402; Manufacturer: TDK; Manufacturer Part Number: CGA2B1X7S1C334KT000F
footprint CAP-0402 (0402 (1005M) Capacitor)
pins: 1, 2

## CGA2B1X7S1C474KT000F
designator C?  Capacitance: 470nF  (hidden comment: *)
Capacitor, Ceramic (MLCC), 470nF, ±10%, 16V, X7S, ±10%, SMD 0402; Manufacturer: TDK; Manufacturer Part Number: CGA2B1X7S1C474KT000F
footprint CAP-0402 (0402 (1005M) Capacitor)
pins: 1, 2

## CGA2B2C0G1H1R5CT0Y0F
designator C?  Capacitance: 1.5pF  (hidden comment: *)
Capacitor, Ceramic (MLCC), 1.5pF, ±0.25pF, 50V, C0G, ±0.25pF, SMD 0402; Manufacturer: TDK; Manufacturer Part Number: CGA2B2C0G1H1R5CT0Y0F
footprint CAP-0402 (0402 (1005M) Capacitor)
pins: 1, 2

## CGA2B2C0G1H2R2CT0Y0F
designator C?  Capacitance: 2.2pF  (hidden comment: *)
Capacitor, Ceramic (MLCC), 2.2pF, ±0.25pF, 50V, C0G, ±0.25pF, SMD 0402; Manufacturer: TDK; Manufacturer Part Number: CGA2B2C0G1H2R2CT0Y0F
footprint CAP-0402 (0402 (1005M) Capacitor)
pins: 1, 2

## CGA2B2C0G1H3R3CT0Y0F
designator C?  Capacitance: 3.3pF  (hidden comment: *)
Capacitor, Ceramic (MLCC), 3.3pF, ±0.25pF, 50V, C0G, ±0.25pF, SMD 0402; Manufacturer: TDK; Manufacturer Part Number: CGA2B2C0G1H3R3CT0Y0F
footprint CAP-0402 (0402 (1005M) Capacitor)
pins: 1, 2

## CGA2B2C0G1H4R7CT0Y0F
designator C?  Capacitance: 4.7pF  (hidden comment: *)
Capacitor, Ceramic (MLCC), 4.7pF, ±0.25pF, 50V, C0G, ±0.25pF, SMD 0402; Manufacturer: TDK; Manufacturer Part Number: CGA2B2C0G1H4R7CT0Y0F
footprint CAP-0402 (0402 (1005M) Capacitor)
pins: 1, 2

## CGA2B2C0G1H6R8DT0Y0F
designator C?  Capacitance: 6.8pF  (hidden comment: *)
Capacitor, Ceramic (MLCC), 6.8pF, ±0.5pF, 50V, C0G, ±0.5pF, SMD 0402; Manufacturer: TDK; Manufacturer Part Number: CGA2B2C0G1H6R8DT0Y0F
footprint CAP-0402 (0402 (1005M) Capacitor)
pins: 1, 2

## CGA2B2C0G1H010CT0Y0F
designator C?  Capacitance: 1pF  (hidden comment: *)
Capacitor, Ceramic (MLCC), 1pF, ±0.25pF, 50V, C0G, ±0.25pF, SMD 0402; Manufacturer: TDK; Manufacturer Part Number: CGA2B2C0G1H010CT0Y0F
footprint CAP-0402 (0402 (1005M) Capacitor)
pins: 1, 2

## CGA2B2C0G1H020CT0Y0F
designator C?  Capacitance: 2pF  (hidden comment: *)
Capacitor, Ceramic (MLCC), 2pF, ±0.25pF, 50V, C0G, ±0.25pF, SMD 0402; Manufacturer: TDK; Manufacturer Part Number: CGA2B2C0G1H020CT0Y0F
footprint CAP-0402 (0402 (1005M) Capacitor)
pins: 1, 2

## CGA2B2C0G1H030CT0Y0F
designator C?  Capacitance: 3pF  (hidden comment: *)
Capacitor, Ceramic (MLCC), 3pF, ±0.25pF, 50V, C0G, ±0.25pF, SMD 0402; Manufacturer: TDK; Manufacturer Part Number: CGA2B2C0G1H030CT0Y0F
footprint CAP-0402 (0402 (1005M) Capacitor)
pins: 1, 2

## CGA2B2C0G1H040CT0Y0F
designator C?  Capacitance: 4pF  (hidden comment: *)
Capacitor, Ceramic (MLCC), 4pF, ±0.25pF, 50V, C0G, ±0.25pF, SMD 0402; Manufacturer: TDK; Manufacturer Part Number: CGA2B2C0G1H040CT0Y0F
footprint CAP-0402 (0402 (1005M) Capacitor)
pins: 1, 2

## CGA2B2C0G1H050CT0Y0F
designator C?  Capacitance: 5pF  (hidden comment: *)
Capacitor, Ceramic (MLCC), 5pF, ±0.25pF, 50V, C0G, ±0.25pF, SMD 0402; Manufacturer: TDK; Manufacturer Part Number: CGA2B2C0G1H050CT0Y0F
footprint CAP-0402 (0402 (1005M) Capacitor)
pins: 1, 2

## CGA2B2C0G1H060DT0Y0F
designator C?  Capacitance: 6pF  (hidden comment: *)
Capacitor, Ceramic (MLCC), 6pF, ±0.5pF, 50V, C0G, ±0.5pF, SMD 0402; Manufacturer: TDK; Manufacturer Part Number: CGA2B2C0G1H060DT0Y0F
footprint CAP-0402 (0402 (1005M) Capacitor)
pins: 1, 2

## CGA2B2C0G1H070DT0Y0F
designator C?  Capacitance: 7pF  (hidden comment: *)
Capacitor, Ceramic (MLCC), 7pF, ±0.5pF, 50V, C0G, ±0.5pF, SMD 0402; Manufacturer: TDK; Manufacturer Part Number: CGA2B2C0G1H070DT0Y0F
footprint CAP-0402 (0402 (1005M) Capacitor)
pins: 1, 2

## CGA2B2C0G1H080DT0Y0F
designator C?  Capacitance: 8pF  (hidden comment: *)
Capacitor, Ceramic (MLCC), 8pF, ±0.5pF, 50V, C0G, ±0.5pF, SMD 0402; Manufacturer: TDK; Manufacturer Part Number: CGA2B2C0G1H080DT0Y0F
footprint CAP-0402 (0402 (1005M) Capacitor)
pins: 1, 2

## CGA2B2C0G1H090DT0Y0F
designator C?  Capacitance: 9pF  (hidden comment: *)
Capacitor, Ceramic (MLCC), 9pF, ±0.5pF, 50V, C0G, ±0.5pF, SMD 0402; Manufacturer: TDK; Manufacturer Part Number: CGA2B2C0G1H090DT0Y0F
footprint CAP-0402 (0402 (1005M) Capacitor)
pins: 1, 2

## CGA2B2C0G1H100DT0Y0F
designator C?  Capacitance: 10pF  (hidden comment: *)
Capacitor, Ceramic (MLCC), 10pF, ±0.5pF, 50V, C0G, ±0.5pF, SMD 0402; Manufacturer: TDK; Manufacturer Part Number: CGA2B2C0G1H100DT0Y0F
footprint CAP-0402 (0402 (1005M) Capacitor)
pins: 1, 2

## CGA2B2C0G1H101JT0Y0F
designator C?  Capacitance: 100pF  (hidden comment: *)
Capacitor, Ceramic (MLCC), 100pF, ±5%, 50V, C0G, ±5%, SMD 0402; Manufacturer: TDK; Manufacturer Part Number: CGA2B2C0G1H101JT0Y0F
footprint CAP-0402 (0402 (1005M) Capacitor)
pins: 1, 2

## CGA2B2C0G1H102JT0Y0F
designator C?  Capacitance: 1nF  (hidden comment: *)
Capacitor, Ceramic (MLCC), 1nF, ±5%, 50V, C0G, ±5%, SMD 0402; Manufacturer: TDK; Manufacturer Part Number: CGA2B2C0G1H102JT0Y0F
footprint CAP-0402 (0402 (1005M) Capacitor)
pins: 1, 2

## CGA2B2C0G1H120JT0Y0F
designator C?  Capacitance: 12pF  (hidden comment: *)
Capacitor, Ceramic (MLCC), 12pF, ±5%, 50V, C0G, ±5%, SMD 0402; Manufacturer: TDK; Manufacturer Part Number: CGA2B2C0G1H120JT0Y0F
footprint CAP-0402 (0402 (1005M) Capacitor)
pins: 1, 2

## CGA2B2C0G1H121JT0Y0F
designator C?  Capacitance: 120pF  (hidden comment: *)
Capacitor, Ceramic (MLCC), 120pF, ±5%, 50V, C0G, ±5%, SMD 0402; Manufacturer: TDK; Manufacturer Part Number: CGA2B2C0G1H121JT0Y0F
footprint CAP-0402 (0402 (1005M) Capacitor)
pins: 1, 2

## CGA2B2C0G1H150JT0Y0F
designator C?  Capacitance: 15pF  (hidden comment: *)
Capacitor, Ceramic (MLCC), 15pF, ±5%, 50V, C0G, ±5%, SMD 0402; Manufacturer: TDK; Manufacturer Part Number: CGA2B2C0G1H150JT0Y0F
footprint CAP-0402 (0402 (1005M) Capacitor)
pins: 1, 2

## CGA2B2C0G1H180JT0Y0F
designator C?  Capacitance: 18pF  (hidden comment: *)
Capacitor, Ceramic (MLCC), 18pF, ±5%, 50V, C0G, ±5%, SMD 0402; Manufacturer: TDK; Manufacturer Part Number: CGA2B2C0G1H180JT0Y0F
footprint CAP-0402 (0402 (1005M) Capacitor)
pins: 1, 2

## CGA2B2C0G1H220JT0Y0F
designator C?  Capacitance: 22pF  (hidden comment: *)
Capacitor, Ceramic (MLCC), 22pF, ±5%, 50V, C0G, ±5%, SMD 0402; Manufacturer: TDK; Manufacturer Part Number: CGA2B2C0G1H220JT0Y0F
footprint CAP-0402 (0402 (1005M) Capacitor)
pins: 1, 2

## CGA2B2C0G1H270JT0Y0F
designator C?  Capacitance: 27pF  (hidden comment: *)
Capacitor, Ceramic (MLCC), 27pF, ±5%, 50V, C0G, ±5%, SMD 0402; Manufacturer: TDK; Manufacturer Part Number: CGA2B2C0G1H270JT0Y0F
footprint CAP-0402 (0402 (1005M) Capacitor)
pins: 1, 2

## CGA2B2C0G1H271JT0Y0F
designator C?  Capacitance: 270pF  (hidden comment: *)
Capacitor, Ceramic (MLCC), 270pF, ±5%, 50V, C0G, ±5%, SMD 0402; Manufacturer: TDK; Manufacturer Part Number: CGA2B2C0G1H271JT0Y0F
footprint CAP-0402 (0402 (1005M) Capacitor)
pins: 1, 2

## CGA2B2C0G1H330JT0Y0F
designator C?  Capacitance: 33pF  (hidden comment: *)
Capacitor, Ceramic (MLCC), 33pF, ±5%, 50V, C0G, ±5%, SMD 0402; Manufacturer: TDK; Manufacturer Part Number: CGA2B2C0G1H330JT0Y0F
footprint CAP-0402 (0402 (1005M) Capacitor)
pins: 1, 2

## CGA2B2C0G1H331JT0Y0F
designator C?  Capacitance: 330pF  (hidden comment: *)
Capacitor, Ceramic (MLCC), 330pF, ±5%, 50V, C0G, ±5%, SMD 0402; Manufacturer: TDK; Manufacturer Part Number: CGA2B2C0G1H331JT0Y0F
footprint CAP-0402 (0402 (1005M) Capacitor)
pins: 1, 2

## CGA2B2C0G1H390JT0Y0F
designator C?  Capacitance: 39pF  (hidden comment: *)
Capacitor, Ceramic (MLCC), 39pF, ±5%, 50V, C0G, ±5%, SMD 0402; Manufacturer: TDK; Manufacturer Part Number: CGA2B2C0G1H390JT0Y0F
footprint CAP-0402 (0402 (1005M) Capacitor)
pins: 1, 2

## CGA2B2C0G1H391JT0Y0F
designator C?  Capacitance: 390pF  (hidden comment: *)
Capacitor, Ceramic (MLCC), 390pF, ±5%, 50V, C0G, ±5%, SMD 0402; Manufacturer: TDK; Manufacturer Part Number: CGA2B2C0G1H391JT0Y0F
footprint CAP-0402 (0402 (1005M) Capacitor)
pins: 1, 2

## CGA2B2C0G1H470JT0Y0F
designator C?  Capacitance: 47pF  (hidden comment: *)
Capacitor, Ceramic (MLCC), 47pF, ±5%, 50V, C0G, ±5%, SMD 0402; Manufacturer: TDK; Manufacturer Part Number: CGA2B2C0G1H470JT0Y0F
footprint CAP-0402 (0402 (1005M) Capacitor)
pins: 1, 2

## CGA2B2C0G1H471JT0Y0F
designator C?  Capacitance: 470pF  (hidden comment: *)
Capacitor, Ceramic (MLCC), 470pF, ±5%, 50V, C0G, ±5%, SMD 0402; Manufacturer: TDK; Manufacturer Part Number: CGA2B2C0G1H471JT0Y0F
footprint CAP-0402 (0402 (1005M) Capacitor)
pins: 1, 2

## CGA2B2C0G1H560JT0Y0F
designator C?  Capacitance: 56pF  (hidden comment: *)
Capacitor, Ceramic (MLCC), 56pF, ±5%, 50V, C0G, ±5%, SMD 0402; Manufacturer: TDK; Manufacturer Part Number: CGA2B2C0G1H560JT0Y0F
footprint CAP-0402 (0402 (1005M) Capacitor)
pins: 1, 2

## CGA2B2C0G1H680JT0Y0F
designator C?  Capacitance: 68pF  (hidden comment: *)
Capacitor, Ceramic (MLCC), 68pF, ±5%, 50V, C0G, ±5%, SMD 0402; Manufacturer: TDK; Manufacturer Part Number: CGA2B2C0G1H680JT0Y0F
footprint CAP-0402 (0402 (1005M) Capacitor)
pins: 1, 2

## CGA2B2C0G1H681JT0Y0F
designator C?  Capacitance: 680pF  (hidden comment: *)
Capacitor, Ceramic (MLCC), 680pF, ±5%, 50V, C0G, ±5%, SMD 0402; Manufacturer: TDK; Manufacturer Part Number: CGA2B2C0G1H681JT0Y0F
footprint CAP-0402 (0402 (1005M) Capacitor)
pins: 1, 2

## CGA2B2C0G1H821JT0Y0F
designator C?  Capacitance: 820pF  (hidden comment: *)
Capacitor, Ceramic (MLCC), 820pF, ±5%, 50V, C0G, ±5%, SMD 0402; Manufacturer: TDK; Manufacturer Part Number: CGA2B2C0G1H821JT0Y0F
footprint CAP-0402 (0402 (1005M) Capacitor)
pins: 1, 2

## CGA2B2NP01H100DT0Y0F
designator C?  Capacitance: 10pF  (hidden comment: *)
Capacitor, Ceramic (MLCC), 10pF, ±0.5pF, 50V, NP0, ±0.5pF, SMD 0402; Manufacturer: TDK; Manufacturer Part Number: CGA2B2NP01H100DT0Y0F
footprint CAP-0402 (0402 (1005M) Capacitor)
pins: 1, 2

## CGA2B2NP01H680JT0Y0F
designator C?  Capacitance: 68pF  (hidden comment: *)
Capacitor, Ceramic (MLCC), 68pF, ±5%, 50V, NP0, ±5%, SMD 0402; Manufacturer: TDK; Manufacturer Part Number: CGA2B2NP01H680JT0Y0F
footprint CAP-0402 (0402 (1005M) Capacitor)
pins: 1, 2

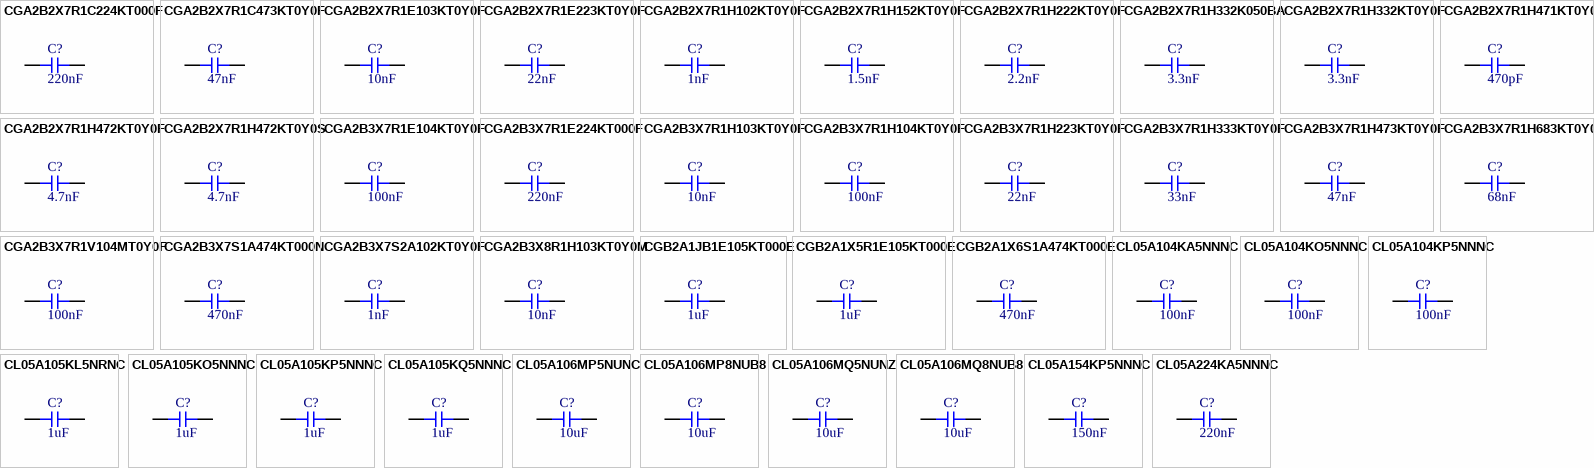
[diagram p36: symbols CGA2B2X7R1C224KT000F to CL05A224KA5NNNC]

## CGA2B2X7R1C224KT000F
designator C?  Capacitance: 220nF  (hidden comment: *)
Capacitor, Ceramic (MLCC), 220nF, ±10%, 16V, X7R, ±10%, SMD 0402; Manufacturer: TDK; Manufacturer Part Number: CGA2B2X7R1C224KT000F
footprint CAP-0402 (0402 (1005M) Capacitor)
pins: 1, 2

## CGA2B2X7R1C473KT0Y0F
designator C?  Capacitance: 47nF  (hidden comment: *)
Capacitor, Ceramic (MLCC), 47nF, ±10%, 16V, X7R, ±10%, SMD 0402; Manufacturer: TDK; Manufacturer Part Number: CGA2B2X7R1C473KT0Y0F
footprint CAP-0402 (0402 (1005M) Capacitor)
pins: 1, 2

## CGA2B2X7R1E103KT0Y0F
designator C?  Capacitance: 10nF  (hidden comment: *)
Capacitor, Ceramic (MLCC), 10nF, ±10%, 25V, X7R, ±10%, SMD 0402; Manufacturer: TDK; Manufacturer Part Number: CGA2B2X7R1E103KT0Y0F
footprint CAP-0402 (0402 (1005M) Capacitor)
pins: 1, 2

## CGA2B2X7R1E223KT0Y0F
designator C?  Capacitance: 22nF  (hidden comment: *)
Capacitor, Ceramic (MLCC), 22nF, ±10%, 25V, X7R, ±10%, SMD 0402; Manufacturer: TDK; Manufacturer Part Number: CGA2B2X7R1E223KT0Y0F
footprint CAP-0402 (0402 (1005M) Capacitor)
pins: 1, 2

## CGA2B2X7R1H102KT0Y0F
designator C?  Capacitance: 1nF  (hidden comment: *)
Capacitor, Ceramic (MLCC), 1nF, ±10%, 50V, X7R, ±10%, SMD 0402; Manufacturer: TDK; Manufacturer Part Number: CGA2B2X7R1H102KT0Y0F
footprint CAP-0402 (0402 (1005M) Capacitor)
pins: 1, 2

## CGA2B2X7R1H152KT0Y0F
designator C?  Capacitance: 1.5nF  (hidden comment: *)
Capacitor, Ceramic (MLCC), 1.5nF, ±10%, 50V, X7R, ±10%, SMD 0402; Manufacturer: TDK; Manufacturer Part Number: CGA2B2X7R1H152KT0Y0F
footprint CAP-0402 (0402 (1005M) Capacitor)
pins: 1, 2

## CGA2B2X7R1H222KT0Y0F
designator C?  Capacitance: 2.2nF  (hidden comment: *)
Capacitor, Ceramic (MLCC), 2.2nF, ±10%, 50V, X7R, ±10%, SMD 0402; Manufacturer: TDK; Manufacturer Part Number: CGA2B2X7R1H222KT0Y0F
footprint CAP-0402 (0402 (1005M) Capacitor)
pins: 1, 2

## CGA2B2X7R1H332K050BA
designator C?  Capacitance: 3.3nF  (hidden comment: *)
Capacitor, Ceramic (MLCC), 3.3nF, ±10%, 50V, X7R, ±10%, SMD 0402; Manufacturer: TDK; Manufacturer Part Number: CGA2B2X7R1H332K050BA
footprint CAP-0402 (0402 (1005M) Capacitor)
pins: 1, 2

## CGA2B2X7R1H332KT0Y0F
designator C?  Capacitance: 3.3nF  (hidden comment: *)
Capacitor, Ceramic (MLCC), 3.3nF, ±10%, 50V, X7R, ±10%, SMD 0402; Manufacturer: TDK; Manufacturer Part Number: CGA2B2X7R1H332KT0Y0F
footprint CAP-0402 (0402 (1005M) Capacitor)
pins: 1, 2

## CGA2B2X7R1H471KT0Y0F
designator C?  Capacitance: 470pF  (hidden comment: *)
Capacitor, Ceramic (MLCC), 470pF, ±10%, 50V, X7R, ±10%, SMD 0402; Manufacturer: TDK; Manufacturer Part Number: CGA2B2X7R1H471KT0Y0F
footprint CAP-0402 (0402 (1005M) Capacitor)
pins: 1, 2

## CGA2B2X7R1H472KT0Y0F
designator C?  Capacitance: 4.7nF  (hidden comment: *)
Capacitor, Ceramic (MLCC), 4.7nF, ±10%, 50V, X7R, ±10%, SMD 0402; Manufacturer: TDK; Manufacturer Part Number: CGA2B2X7R1H472KT0Y0F
footprint CAP-0402 (0402 (1005M) Capacitor)
pins: 1, 2

## CGA2B2X7R1H472KT0Y0S
designator C?  Capacitance: 4.7nF  (hidden comment: *)
Capacitor, Ceramic (MLCC), 4.7nF, ±10%, 50V, X7R, ±10%, SMD 0402; Manufacturer: TDK; Manufacturer Part Number: CGA2B2X7R1H472KT0Y0S
footprint CAP-0402 (0402 (1005M) Capacitor)
pins: 1, 2

## CGA2B3X7R1E104KT0Y0F
designator C?  Capacitance: 100nF  (hidden comment: *)
Capacitor, Ceramic (MLCC), 100nF, ±10%, 25V, X7R, ±10%, SMD 0402; Manufacturer: TDK; Manufacturer Part Number: CGA2B3X7R1E104KT0Y0F
footprint CAP-0402 (0402 (1005M) Capacitor)
pins: 1, 2

## CGA2B3X7R1E224KT000F
designator C?  Capacitance: 220nF  (hidden comment: *)
Capacitor, Ceramic (MLCC), 220nF, ±10%, 25V, X7R, ±10%, SMD 0402; Manufacturer: TDK; Manufacturer Part Number: CGA2B3X7R1E224KT000F
footprint CAP-0402 (0402 (1005M) Capacitor)
pins: 1, 2

## CGA2B3X7R1H103KT0Y0F
designator C?  Capacitance: 10nF  (hidden comment: *)
Capacitor, Ceramic (MLCC), 10nF, ±10%, 50V, X7R, ±10%, SMD 0402; Manufacturer: TDK; Manufacturer Part Number: CGA2B3X7R1H103KT0Y0F
footprint CAP-0402 (0402 (1005M) Capacitor)
pins: 1, 2

## CGA2B3X7R1H104KT0Y0F
designator C?  Capacitance: 100nF  (hidden comment: *)
Capacitor, Ceramic (MLCC), 100nF, ±10%, 50V, X7R, ±10%, SMD 0402; Manufacturer: TDK; Manufacturer Part Number: CGA2B3X7R1H104KT0Y0F
footprint CAP-0402 (0402 (1005M) Capacitor)
pins: 1, 2

## CGA2B3X7R1H223KT0Y0F
designator C?  Capacitance: 22nF  (hidden comment: *)
Capacitor, Ceramic (MLCC), 22nF, ±10%, 50V, X7R, ±10%, SMD 0402; Manufacturer: TDK; Manufacturer Part Number: CGA2B3X7R1H223KT0Y0F
footprint CAP-0402 (0402 (1005M) Capacitor)
pins: 1, 2

## CGA2B3X7R1H333KT0Y0F
designator C?  Capacitance: 33nF  (hidden comment: *)
Capacitor, Ceramic (MLCC), 33nF, ±10%, 50V, X7R, ±10%, SMD 0402; Manufacturer: TDK; Manufacturer Part Number: CGA2B3X7R1H333KT0Y0F
footprint CAP-0402 (0402 (1005M) Capacitor)
pins: 1, 2

## CGA2B3X7R1H473KT0Y0F
designator C?  Capacitance: 47nF  (hidden comment: *)
Capacitor, Ceramic (MLCC), 47nF, ±10%, 50V, X7R, ±10%, SMD 0402; Manufacturer: TDK; Manufacturer Part Number: CGA2B3X7R1H473KT0Y0F
footprint CAP-0402 (0402 (1005M) Capacitor)
pins: 1, 2

## CGA2B3X7R1H683KT0Y0F
designator C?  Capacitance: 68nF  (hidden comment: *)
Capacitor, Ceramic (MLCC), 68nF, ±10%, 50V, X7R, ±10%, SMD 0402; Manufacturer: TDK; Manufacturer Part Number: CGA2B3X7R1H683KT0Y0F
footprint CAP-0402 (0402 (1005M) Capacitor)
pins: 1, 2

## CGA2B3X7R1V104MT0Y0F
designator C?  Capacitance: 100nF  (hidden comment: *)
Capacitor, Ceramic (MLCC), 100nF, ±20%, 35V, X7R, ±20%, SMD 0402; Manufacturer: TDK; Manufacturer Part Number: CGA2B3X7R1V104MT0Y0F
footprint CAP-0402 (0402 (1005M) Capacitor)
pins: 1, 2

## CGA2B3X7S1A474KT000N
designator C?  Capacitance: 470nF  (hidden comment: *)
Capacitor, Ceramic (MLCC), 470nF, ±10%, 10V, X7S, ±10%, SMD 0402; Manufacturer: TDK; Manufacturer Part Number: CGA2B3X7S1A474KT000N
footprint CAP-0402 (0402 (1005M) Capacitor)
pins: 1, 2

## CGA2B3X7S2A102KT0Y0F
designator C?  Capacitance: 1nF  (hidden comment: *)
Capacitor, Ceramic (MLCC), 1nF, ±10%, 100V, X7S, ±10%, SMD 0402; Manufacturer: TDK; Manufacturer Part Number: CGA2B3X7S2A102KT0Y0F
footprint CAP-0402 (0402 (1005M) Capacitor)
pins: 1, 2

## CGA2B3X8R1H103KT0Y0M
designator C?  Capacitance: 10nF  (hidden comment: *)
Capacitor, Ceramic (MLCC), 10nF, ±10%, 50V, X8R, ±10%, SMD 0402; Manufacturer: TDK; Manufacturer Part Number: CGA2B3X8R1H103KT0Y0M
footprint CAP-0402 (0402 (1005M) Capacitor)
pins: 1, 2

## CGB2A1JB1E105KT000E
designator C?  Capacitance: 1uF  (hidden comment: *)
Capacitor, Ceramic (MLCC), 1uF, ±10%, 25V, JB, ±10%, SMD 0402; Manufacturer: TDK; Manufacturer Part Number: CGB2A1JB1E105KT000E
footprint CAP-0402 (0402 (1005M) Capacitor)
pins: 1, 2

## CGB2A1X5R1E105KT000E
designator C?  Capacitance: 1uF  (hidden comment: *)
Capacitor, Ceramic (MLCC), 1uF, ±10%, 25V, X5R, ±10%, SMD 0402; Manufacturer: TDK; Manufacturer Part Number: CGB2A1X5R1E105KT000E
footprint CAP-0402 (0402 (1005M) Capacitor)
pins: 1, 2

## CGB2A1X6S1A474KT000E
designator C?  Capacitance: 470nF  (hidden comment: *)
Capacitor, Ceramic (MLCC), 470nF, ±10%, 10V, X6S, ±10%, SMD 0402; Manufacturer: TDK; Manufacturer Part Number: CGB2A1X6S1A474KT000E
footprint CAP-0402 (0402 (1005M) Capacitor)
pins: 1, 2

## CL05A104KA5NNNC
designator C?  Capacitance: 100nF  (hidden comment: *)
Capacitor, Ceramic (MLCC), 100nF, ±10%, 25V, X5R, ±10%, SMD 0402; Manufacturer: Samsung Electro-Mechanics; Manufacturer Part Number: CL05A104KA5NNNC
footprint CAP-0402 (0402 (1005M) Capacitor)
pins: 1, 2

## CL05A104KO5NNNC
designator C?  Capacitance: 100nF  (hidden comment: *)
Capacitor, Ceramic (MLCC), 100nF, ±10%, 16V, X5R, ±10%, SMD 0402; Manufacturer: Samsung Electro-Mechanics; Manufacturer Part Number: CL05A104KO5NNNC
footprint CAP-0402 (0402 (1005M) Capacitor)
pins: 1, 2

## CL05A104KP5NNNC
designator C?  Capacitance: 100nF  (hidden comment: *)
Capacitor, Ceramic (MLCC), 100nF, ±10%, 10V, X5R, ±10%, SMD 0402; Manufacturer: Samsung Electro-Mechanics; Manufacturer Part Number: CL05A104KP5NNNC
footprint CAP-0402 (0402 (1005M) Capacitor)
pins: 1, 2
